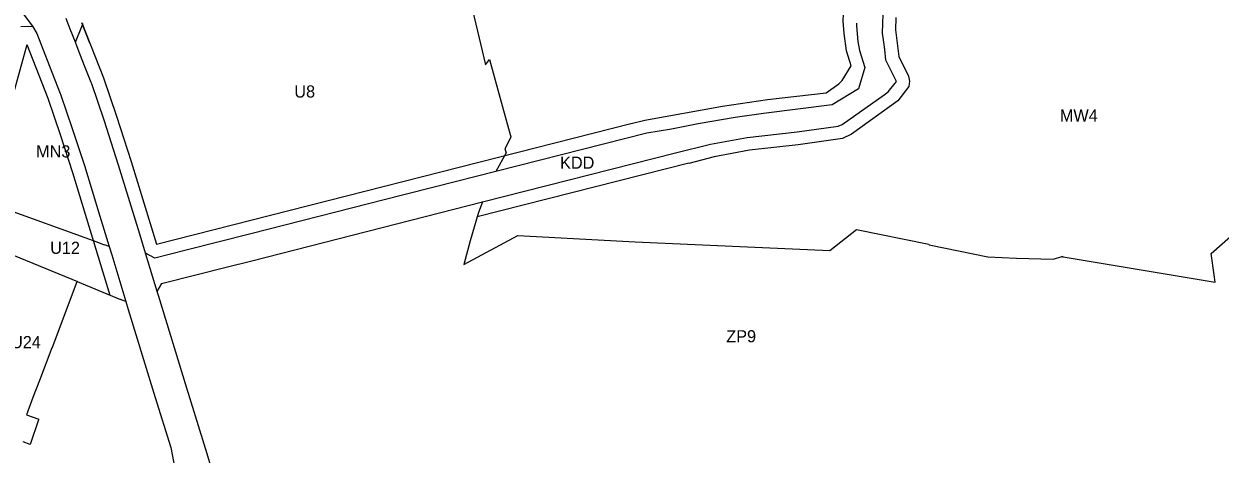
# Model space of a CAD drawing. Extents: x 7428080 to 7432143, y 5545880 to 5549217.
# Drawn here: x 7429340 to 7429887, y 5548288 to 5548485 of the extents above; entities that cross this region are included whole.
import ezdxf

# ---------------------------------------------------------------- set-up
doc = ezdxf.new("R2010")
doc.units = 0
for name, color, linetype in [('CZ_L_linie rozgraniczające tereny o różnym przeznaczeniu oraz różnych warunkach ich zabudowy i zagospodarowania', 7, 'Continuous'), ('CZ_L_maksymalne nieprzekraczalne linie zabudowy', 7, 'Continuous'), ('CZ_L_opisy_linie rozgraniczające tereny o różnym przeznaczeniu oraz różnych warunkach ich zabudowy i zagospodarowania', 7, 'Continuous')]:
    doc.layers.add(name, color=color, linetype=linetype)

msp = doc.modelspace()

# ---------------------------------------------------------------- linework, layer by layer
at = {"layer": 'CZ_L_linie rozgraniczające tereny o różnym przeznaczeniu oraz różnych warunkach ich zabudowy i zagospodarowania'}
for p, q in [((7429331.62, 5548500.25), (7429344.19, 5548483.46)), ((7429542.72, 5548501.72), (7429551.2, 5548465.86)), ((7429732.49, 5548480.24), (7429732.99, 5548493.43)), ((7429361.52, 5548482.07), (7429359.57, 5548487.06)), ((7429338.93, 5548483.39), (7429344.19, 5548483.46)), ((7429344.19, 5548483.46), (7429346.2, 5548480.18)), ((7429363.82, 5548476.18), (7429361.52, 5548482.07)), ((7429363.82, 5548476.18), (7429366.8, 5548483.37)), ((7429366.8, 5548483.37), (7429367.36, 5548484.72)), ((7429720.58, 5548484.92), (7429720.52, 5548483.63)), ((7429720.52, 5548483.63), (7429721.17, 5548476.46)), ((7429346.2, 5548480.18), (7429350.9, 5548468.02)), ((7429364.61, 5548474.14), (7429363.82, 5548476.18)), ((7429721.17, 5548476.46), (7429722, 5548472.38)), ((7429733.1, 5548476.2), (7429732.49, 5548480.24)), ((7429733.5, 5548472.85), (7429733.1, 5548476.2)), ((7429365.87, 5548470.92), (7429364.61, 5548474.14)), ((7429368.36, 5548464.56), (7429365.87, 5548470.92)), ((7429722, 5548472.38), (7429722, 5548472.38)), ((7429722, 5548472.38), (7429724.42, 5548464.58)), ((7429733.97, 5548467.96), (7429733.5, 5548472.85)), ((7429350.9, 5548468.02), (7429356.89, 5548452.77)), ((7429551.2, 5548465.86), (7429552.92, 5548468.23)), ((7429552.92, 5548468.23), (7429559.36, 5548445.05)), ((7429724.42, 5548464.58), (7429724.41, 5548464.57)), ((7429734.4, 5548467.1), (7429733.97, 5548467.96)), ((7429738.88, 5548458.19), (7429734.4, 5548467.1)), ((7429371.1, 5548457.78), (7429368.36, 5548464.56)), ((7429371.28, 5548457.15), (7429371.1, 5548457.78)), ((7429376.91, 5548440.56), (7429371.28, 5548457.15)), ((7429721.57, 5548454.89), (7429709.45, 5548447.55)), ((7429735.02, 5548453.51), (7429738.88, 5548458.19)), ((7429356.89, 5548452.77), (7429357.03, 5548452.41)), ((7429357.03, 5548452.41), (7429357.14, 5548452.02)), ((7429357.14, 5548452.02), (7429362.38, 5548436.71)), ((7429714.03, 5548438.55), (7429733.21, 5548452.09)), ((7429733.21, 5548452.09), (7429733.23, 5548452.11)), ((7429733.23, 5548452.11), (7429735.02, 5548453.51)), ((7429559.36, 5548445.05), (7429562.71, 5548432.99)), ((7429678.17, 5548443.56), (7429665.23, 5548441.84)), ((7429709.45, 5548447.55), (7429678.17, 5548443.56)), ((7429383.57, 5548419.96), (7429376.91, 5548440.56)), ((7429648.29, 5548438.84), (7429636.1, 5548436.45)), ((7429665.23, 5548441.84), (7429648.29, 5548438.84)), ((7429693.48, 5548435.23), (7429712.21, 5548437.85)), ((7429712.21, 5548437.85), (7429714.03, 5548438.55)), ((7429362.38, 5548436.71), (7429367.93, 5548419.79)), ((7429624.89, 5548434.67), (7429555.85, 5548417.11)), ((7429562.71, 5548432.99), (7429560.09, 5548427.59)), ((7429636.1, 5548436.45), (7429624.89, 5548434.67)), ((7429653.92, 5548429.67), (7429670.63, 5548432.65)), ((7429670.63, 5548432.65), (7429693.48, 5548435.23)), ((7429560.06, 5548427.52), (7429560.04, 5548427.48)), ((7429560.04, 5548427.48), (7429560.52, 5548425.69)), ((7429560.09, 5548427.59), (7429560.06, 5548427.53)), ((7429560.06, 5548427.53), (7429560.06, 5548427.52)), ((7429637.98, 5548425.61), (7429653.92, 5548429.67)), ((7429549.78, 5548403.19), (7429637.98, 5548425.61)), ((7429560.52, 5548425.69), (7429555.85, 5548417.11)), ((7429367.93, 5548419.79), (7429375, 5548396.73)), ((7429393.2, 5548388.55), (7429383.57, 5548419.96)), ((7429555.85, 5548417.11), (7429528.33, 5548410.12)), ((7429528.33, 5548410.12), (7429513.3, 5548406.3)), ((7429373.74, 5548384.85), (7429316.88, 5548405.29)), ((7429513.3, 5548406.3), (7429443.95, 5548388.66)), ((7429444.36, 5548376.39), (7429549.78, 5548403.19)), ((7429549.78, 5548403.19), (7429547.82, 5548397.93)), ((7429375, 5548396.73), (7429379.25, 5548382.86)), ((7429547.82, 5548397.93), (7429544.18, 5548385.45)), ((7429395.87, 5548379.8), (7429393.2, 5548388.55)), ((7429443.95, 5548388.66), (7429414.41, 5548381.15)), ((7429708.48, 5548380.98), (7429720.54, 5548390.67)), ((7429720.54, 5548390.67), (7429753.57, 5548383.95)), ((7429377.21, 5548383.51), (7429373.74, 5548384.85)), ((7429379.25, 5548382.86), (7429377.18, 5548383.61)), ((7429377.18, 5548383.61), (7429377.21, 5548383.51)), ((7429379.25, 5548382.86), (7429380.42, 5548379.04)), ((7429541.3, 5548374.61), (7429565.87, 5548387.95)), ((7429544.18, 5548385.45), (7429541.3, 5548374.61)), ((7429565.87, 5548387.95), (7429619.5, 5548385.06)), ((7429619.5, 5548385.06), (7429708.48, 5548380.98)), ((7429753.57, 5548383.95), (7429753.84, 5548383.66)), ((7429753.84, 5548383.66), (7429780.61, 5548378.2)), ((7429882.63, 5548379.71), (7429891.41, 5548387.5)), ((7429380.42, 5548379.04), (7429386.93, 5548357.7)), ((7429401.23, 5548362.24), (7429395.87, 5548379.8)), ((7429400.08, 5548377.56), (7429395.87, 5548379.8)), ((7429414.41, 5548381.15), (7429400.08, 5548377.56)), ((7429780.61, 5548378.2), (7429793.66, 5548377.55)), ((7429793.66, 5548377.55), (7429810.39, 5548377.05)), ((7429810.39, 5548377.05), (7429814.57, 5548378.32)), ((7429814.57, 5548378.32), (7429814.53, 5548378.45)), ((7429814.53, 5548378.45), (7429814.92, 5548378.2)), ((7429814.92, 5548378.2), (7429884.42, 5548366.51)), ((7429883.95, 5548369.97), (7429882.63, 5548379.71)), ((7429404.39, 5548366.22), (7429432.67, 5548373.41)), ((7429432.67, 5548373.41), (7429444.36, 5548376.39)), ((7429884.42, 5548366.51), (7429883.95, 5548369.97)), ((7429401.23, 5548362.24), (7429403.32, 5548365.95)), ((7429401.77, 5548360.44), (7429401.23, 5548362.24)), ((7429403.32, 5548365.95), (7429404.39, 5548366.22)), ((7429386.93, 5548357.7), (7429388.02, 5548354.11)), ((7429414.75, 5548318.17), (7429401.77, 5548360.44)), ((7429388.02, 5548354.11), (7429395.02, 5548331.3)), ((7429395.02, 5548331.3), (7429400.35, 5548313.95)), ((7429423.96, 5548288.2), (7429414.75, 5548318.17)), ((7429400.35, 5548313.95), (7429407.37, 5548291.1)), ((7429407.37, 5548291.1), (7429410.76, 5548273.99)), ((7429426.99, 5548278.37), (7429423.96, 5548288.2))]:
    msp.add_line(p, q, dxfattribs=at)
for points in [[(7429724.41, 5548464.57), (7429721.57, 5548454.89)], [(7429311.75, 5548388.53), (7429311.92, 5548388.46), (7429364.74, 5548366.81), (7429364.8, 5548366.69)], [(7429364.8, 5548366.68), (7429364.56, 5548366.78), (7429353.17, 5548336.76), (7429353.18, 5548336.53), (7429353.02, 5548336.6), (7429347.38, 5548321.65), (7429344.45, 5548313.86), (7429341.48, 5548305.99), (7429347.09, 5548303.97), (7429347.05, 5548303.86), (7429347.01, 5548303.73), (7429343.2, 5548292.46), (7429343.19, 5548292.43), (7429343.19, 5548292.42), (7429343.19, 5548292.42), (7429339.97, 5548293.62), (7429339.94, 5548293.49)], [(7429386.93, 5548357.7), (7429384.52, 5548358.63), (7429384.54, 5548358.54), (7429364.81, 5548366.68), (7429364.8, 5548366.69)], [(7429364.81, 5548366.68), (7429364.8, 5548366.68)], [(7429364.8, 5548366.68), (7429364.8, 5548366.68)]]:
    msp.add_lwpolyline(points, dxfattribs=at)
at = {"layer": 'CZ_L_maksymalne nieprzekraczalne linie zabudowy'}
for points in [[(7429617.63, 5548439.11), (7429623.98, 5548440.62), (7429659.34, 5548446.97), (7429679.98, 5548449.94), (7429706.66, 5548453.04), (7429712.54, 5548457.18), (7429714.11, 5548458.63), (7429718.11, 5548465.46), (7429716.07, 5548472.3), (7429714.99, 5548480.18), (7429714.51, 5548485.82), (7429715.05, 5548499.33)], [(7429738.61, 5548487.43), (7429738.34, 5548481.76), (7429739.9, 5548469.67), (7429744.35, 5548460.73), (7429744.82, 5548458.36), (7429744.42, 5548455.96), (7429739.4, 5548449.33), (7429718.28, 5548434.17), (7429714.22, 5548432.23), (7429693.91, 5548429.24), (7429671.73, 5548426.83), (7429655.62, 5548423.79), (7429644.04, 5548420.8)], [(7429370.44, 5548475.74), (7429366.81, 5548484.98), (7429376.69, 5548459.93), (7429382.61, 5548442.42), (7429389.3, 5548421.73), (7429400.87, 5548383.94), (7429617.45, 5548438.97)], [(7429341.66, 5548475.02), (7429335.21, 5548451.88), (7429320.74, 5548397.16), (7429310.09, 5548363.49), (7429299.06, 5548334.66), (7429287.9, 5548308.54), (7429279.42, 5548283.92), (7429270.71, 5548265.21)], [(7429379.79, 5548360.52), (7429362.68, 5548416.45), (7429357.01, 5548433.82), (7429351.35, 5548450.46), (7429341.78, 5548474.97)], [(7429644.04, 5548420.97), (7429547.33, 5548396.38)]]:
    msp.add_lwpolyline(points, dxfattribs=at)

# ---------------------------------------------------------------- texts
at = {"layer": 'CZ_L_opisy_linie rozgraniczające tereny o różnym przeznaczeniu oraz różnych warunkach ich zabudowy i zagospodarowania'}
for s, p in [('U8', (7429463.83, 5548450.9)), ('MW4', (7429813.47, 5548439.93)), ('MN3', (7429345.89, 5548423.53)), ('KDD', (7429585.2, 5548418.38)), ('U12', (7429352.32, 5548379.51)), ('ZP9', (7429661.11, 5548339.09)), ('MU24', (7429328.28, 5548336.42))]:
    msp.add_text(s, height=5.549, dxfattribs=at).set_placement(p)

doc.saveas('drawing.dxf')
